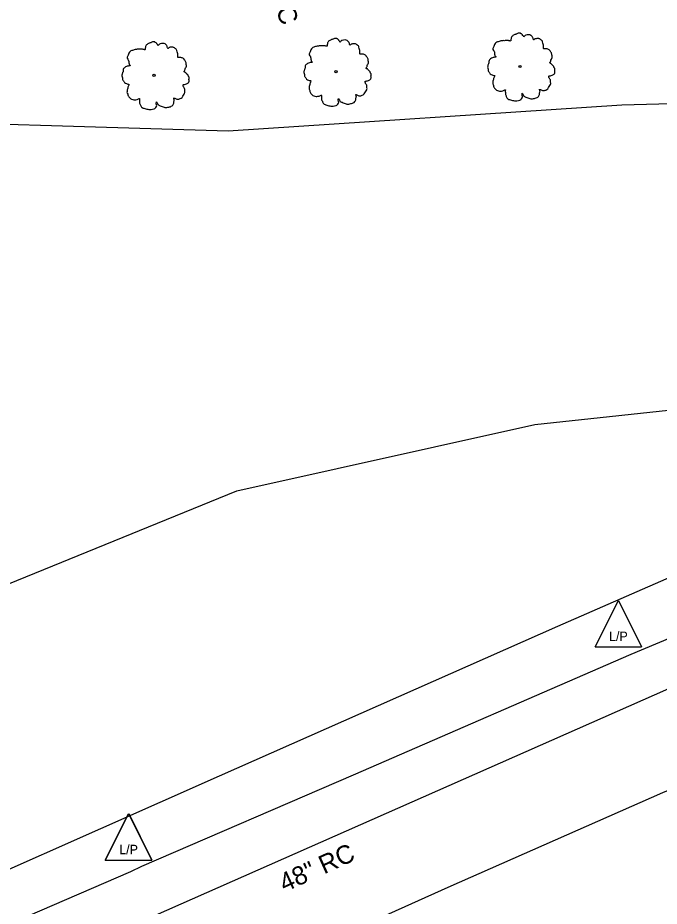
# Model space of a CAD drawing. Extents: x 2004847 to 2009016, y 1134161 to 1140101.
# Drawn here: x 2006951.1 to 2007089.2, y 1137199.9 to 1137391.2 of the extents above; entities that cross this region are included whole.
import ezdxf

# ---------------------------------------------------------------- set-up
doc = ezdxf.new("R2010")
doc.units = 0
for name, color, linetype in [('RD_EX_DR_Pipe', 7, 'Continuous'), ('RD_EX_DR_Pipe_txCode', 7, 'Continuous'), ('RD_EX_Fence_ChLk', 7, 'Continuous'), ('RD_EX_Road', 7, 'Continuous'), ('RD_EX_UT', 7, 'Continuous'), ('RD_EX_VEG', 7, 'Continuous'), ('RD_Sketch3', 7, 'Continuous')]:
    doc.layers.add(name, color=color, linetype=linetype)

msp = doc.modelspace()

# ---------------------------------------------------------------- linework, layer by layer
at = {"layer": 'RD_EX_DR_Pipe'}
msp.add_line((2007177.46, 1137284.68), (2006880.54, 1137153.79), dxfattribs=at)
at = {"layer": 'RD_EX_Fence_ChLk'}
msp.add_lwpolyline([(2006679.24, 1137088.33), (2006760.68, 1137124.45), (2006840.06, 1137159.61), (2006918.41, 1137194.25), (2006994.49, 1137227.96), (2007067.38, 1137260.2), (2007099.31, 1137274.1), (2007109.34, 1137278.47), (2007154.43, 1137298.36), (2007228.48, 1137300.45), (2007306.83, 1137302.12), (2007383.88, 1137303.46)], dxfattribs=at)
at = {"layer": 'RD_EX_Road'}
for points in [[(2006977.78, 1137208.53), (2007023.41, 1137228.21), (2007083.18, 1137254.16), (2007127.4, 1137272.66), (2007144.23, 1137278.54), (2007157.04, 1137281.53), (2007170.48, 1137283.07), (2007177.18, 1137282.69), (2007180.46, 1137282.8), (2007189.97, 1137283.94), (2007250.02, 1137285.07), (2007315.48, 1137286.29), (2007381.64, 1137287.47)], [(2007347.33, 1137031.69), (2007356.56, 1137042.98), (2007358.71, 1137060.56), (2007338.63, 1137108.3), (2007311.34, 1137170.6), (2007285.8, 1137228.92), (2007261.01, 1137249.76), (2007245.66, 1137254.82), (2007196.64, 1137254.34), (2007160.77, 1137251.15), (2007126.25, 1137239.56), (2007089.93, 1137224.32), (2007043.69, 1137203.9), (2006991.12, 1137180.28), (2006988, 1137178.88)], [(2006775.35, 1136676.67), (2006777.94, 1136681.79), (2006766.22, 1136711.06), (2006750.72, 1136746.34), (2006732.8, 1136787.49), (2006716.56, 1136823.39), (2006692.62, 1136878.29), (2006667.71, 1136935.76), (2006658.83, 1136989.32), (2006664.28, 1137021.7), (2006686.47, 1137064.98), (2006711.13, 1137087.73), (2006777.9, 1137121.36), (2006828.33, 1137143.11), (2006876.2, 1137164.06), (2006930.82, 1137188.1), (2006975.41, 1137207.33), (2006977.78, 1137208.53)]]:
    msp.add_lwpolyline(points, dxfattribs=at)
at = {"layer": 'RD_EX_UT'}
for p, q in [((2007075.45, 1137255.72), (2007080.45, 1137265.72)), ((2007080.45, 1137265.72), (2007085.45, 1137255.72)), ((2007075.45, 1137255.72), (2007085.45, 1137255.72)), ((2006969.93, 1137209.81), (2006974.93, 1137219.81)), ((2006969.96, 1137209.83), (2006974.96, 1137219.83)), ((2006974.93, 1137219.81), (2006979.93, 1137209.81)), ((2006974.96, 1137219.83), (2006979.96, 1137209.83)), ((2006969.93, 1137209.81), (2006979.93, 1137209.81)), ((2006969.96, 1137209.83), (2006979.96, 1137209.83))]:
    msp.add_line(p, q, dxfattribs=at)
at = {"layer": 'RD_EX_VEG'}
for points in [[(2007286.19, 1137375.92), (2007274.32, 1137376.1), (2007246.66, 1137372.59), (2007163.36, 1137374.54), (2007081.16, 1137372.35), (2006996.36, 1137366.78), (2006910.64, 1137369.33), (2006829.66, 1137367.22), (2006737.12, 1137362.87)], [(2006471.18, 1137129.79), (2006480.26, 1137120.14), (2006535.33, 1137102.81), (2006642, 1137137.54), (2006697.24, 1137155.67), (2006783.81, 1137195.08), (2006842.32, 1137220.43), (2006911.16, 1137253.85), (2006998.26, 1137289.33), (2007062.47, 1137303.6), (2007136.1, 1137311.49), (2007186.51, 1137309.69), (2007295.5, 1137306.98), (2007351.72, 1137306.99), (2007387.72, 1137305.5)]]:
    msp.add_lwpolyline(points, dxfattribs=at)
for centre, radius in [((2007059.22, 1137380.67), 0.25), ((2007059.2, 1137380.65), 0.0001), ((2006980.44, 1137378.8), 0.25), ((2006980.43, 1137378.78), 0.0001), ((2007019.65, 1137379.54), 0.25), ((2007019.64, 1137379.52), 0.0001)]:
    msp.add_circle(centre, radius, dxfattribs=at)
for points in [[(2007059.35, 1137387.83), (2007059.05, 1137387.86), (2007058.72, 1137387.76), (2007058.47, 1137387.66), (2007058.25, 1137387.58), (2007058.02, 1137387.48), (2007057.72, 1137387.31), (2007057.5, 1137387.11), (2007057.37, 1137386.86), (2007057.32, 1137386.63), (2007057.27, 1137386.36), (2007057.27, 1137386.18), (2007057.15, 1137386.16), (2007057, 1137386.18), (2007056.75, 1137386.26), (2007056.5, 1137386.26), (2007056.25, 1137386.26), (2007055.9, 1137386.23), (2007055.55, 1137386.23), (2007055.27, 1137386.18), (2007054.95, 1137386.14), (2007054.58, 1137386.01), (2007054.23, 1137385.89), (2007053.93, 1137385.64), (2007053.68, 1137385.16), (2007053.55, 1137384.81), (2007053.4, 1137384.56), (2007053.55, 1137384.11), (2007053.73, 1137383.76), (2007053.75, 1137383.56), (2007053.83, 1137383.14), (2007053.93, 1137382.91), (2007054.05, 1137382.71), (2007053.98, 1137382.69), (2007053.6, 1137382.64), (2007053.3, 1137382.54), (2007052.88, 1137382.31), (2007052.65, 1137382.09), (2007052.55, 1137381.76), (2007052.53, 1137381.41), (2007052.43, 1137381.21), (2007052.35, 1137380.94), (2007052.33, 1137380.86), (2007052.28, 1137380.54), (2007052.38, 1137380.09), (2007052.4, 1137379.74), (2007052.53, 1137379.51), (2007052.68, 1137379.34), (2007052.85, 1137379.09), (2007053.25, 1137378.86), (2007053.58, 1137378.76), (2007053.78, 1137378.74), (2007053.6, 1137378.24), (2007053.55, 1137377.89), (2007053.43, 1137377.49), (2007053.43, 1137377.41), (2007053.38, 1137376.94), (2007053.53, 1137376.61), (2007053.6, 1137376.24), (2007053.78, 1137376.01), (2007054.05, 1137375.71), (2007054.38, 1137375.49), (2007054.87, 1137375.36), (2007055.27, 1137375.39), (2007055.85, 1137375.56), (2007056.1, 1137375.64), (2007056.07, 1137375.46), (2007056.1, 1137375.09), (2007056.1, 1137374.67), (2007056.25, 1137374.34), (2007056.35, 1137374.07), (2007056.5, 1137373.82), (2007056.82, 1137373.59), (2007057.22, 1137373.52), (2007057.65, 1137373.37), (2007058.1, 1137373.29), (2007058.6, 1137373.27), (2007059.2, 1137373.42), (2007059.47, 1137373.54), (2007059.57, 1137373.72), (2007059.77, 1137374.09), (2007059.72, 1137374.32), (2007059.75, 1137374.91), (2007059.85, 1137374.74), (2007060.02, 1137374.39), (2007060.52, 1137374.09), (2007060.92, 1137373.92), (2007061.4, 1137373.77), (2007061.7, 1137373.69), (2007062.17, 1137373.77), (2007062.55, 1137373.84), (2007062.92, 1137373.97), (2007063.22, 1137374.24), (2007063.4, 1137374.52), (2007063.45, 1137374.79), (2007063.52, 1137375.16), (2007063.57, 1137375.34)], [(2007063.57, 1137375.34), (2007063.5, 1137375.51), (2007063.45, 1137375.76), (2007063.52, 1137375.74), (2007063.7, 1137375.69), (2007063.97, 1137375.56), (2007064.2, 1137375.49), (2007064.52, 1137375.51), (2007064.8, 1137375.61), (2007065.25, 1137375.89), (2007065.52, 1137376.36), (2007065.8, 1137376.76), (2007065.87, 1137377.09), (2007065.82, 1137377.31), (2007065.8, 1137377.81), (2007065.6, 1137378.06), (2007065.55, 1137378.19), (2007065.45, 1137378.59), (2007065.52, 1137378.64), (2007065.8, 1137378.69), (2007066.17, 1137378.81), (2007066.44, 1137378.94), (2007066.67, 1137379.11), (2007066.74, 1137379.34), (2007066.72, 1137379.74), (2007066.77, 1137380.14), (2007066.69, 1137380.29), (2007066.59, 1137380.44), (2007066.52, 1137380.64), (2007066.37, 1137380.79), (2007066.27, 1137380.94), (2007066.17, 1137381.04), (2007066.05, 1137381.19), (2007065.87, 1137381.31), (2007065.72, 1137381.36), (2007065.67, 1137381.51), (2007065.82, 1137381.71), (2007065.87, 1137381.81), (2007065.9, 1137382.04), (2007066.12, 1137382.39), (2007066.17, 1137382.79), (2007066.12, 1137383.21), (2007066.07, 1137383.49), (2007065.92, 1137383.76), (2007065.72, 1137384.01), (2007065.6, 1137384.19), (2007065.42, 1137384.31), (2007065.1, 1137384.44), (2007064.85, 1137384.49), (2007064.5, 1137384.49), (2007064.3, 1137384.54), (2007064.32, 1137384.59), (2007064.32, 1137384.74), (2007064.32, 1137385.01), (2007064.25, 1137385.46), (2007064.1, 1137385.96), (2007064.1, 1137385.99), (2007064, 1137386.23), (2007063.77, 1137386.43), (2007063.6, 1137386.53), (2007063.4, 1137386.66), (2007063.15, 1137386.68), (2007062.85, 1137386.68), (2007062.57, 1137386.63), (2007062.37, 1137386.53), (2007062.2, 1137386.41), (2007062.12, 1137386.56), (2007062.02, 1137386.86), (2007061.97, 1137387.01), (2007061.82, 1137387.18), (2007061.6, 1137387.38), (2007061.15, 1137387.51), (2007060.52, 1137387.43), (2007060.22, 1137387.23), (2007060.07, 1137387.06), (2007060.02, 1137387.18), (2007059.82, 1137387.38), (2007059.72, 1137387.56), (2007059.55, 1137387.68), (2007059.4, 1137387.78), (2007059.3, 1137387.83)], [(2006980.57, 1137385.97), (2006980.27, 1137385.99), (2006979.95, 1137385.89), (2006979.7, 1137385.79), (2006979.47, 1137385.72), (2006979.25, 1137385.62), (2006978.95, 1137385.44), (2006978.72, 1137385.24), (2006978.6, 1137384.99), (2006978.55, 1137384.77), (2006978.5, 1137384.49), (2006978.5, 1137384.32), (2006978.37, 1137384.29), (2006978.22, 1137384.32), (2006977.97, 1137384.39), (2006977.72, 1137384.39), (2006977.47, 1137384.39), (2006977.12, 1137384.37), (2006976.77, 1137384.37), (2006976.5, 1137384.32), (2006976.17, 1137384.27), (2006975.8, 1137384.14), (2006975.45, 1137384.02), (2006975.15, 1137383.77), (2006974.9, 1137383.29), (2006974.77, 1137382.94), (2006974.62, 1137382.69), (2006974.77, 1137382.24), (2006974.95, 1137381.9), (2006974.97, 1137381.7), (2006975.05, 1137381.27), (2006975.15, 1137381.05), (2006975.27, 1137380.85), (2006975.2, 1137380.82), (2006974.82, 1137380.77), (2006974.52, 1137380.67), (2006974.1, 1137380.45), (2006973.87, 1137380.22), (2006973.77, 1137379.9), (2006973.75, 1137379.55), (2006973.65, 1137379.35), (2006973.57, 1137379.07), (2006973.55, 1137379), (2006973.5, 1137378.67), (2006973.6, 1137378.22), (2006973.62, 1137377.87), (2006973.75, 1137377.65), (2006973.9, 1137377.47), (2006974.07, 1137377.22), (2006974.47, 1137377), (2006974.8, 1137376.9), (2006975, 1137376.87), (2006974.82, 1137376.37), (2006974.77, 1137376.02), (2006974.65, 1137375.62), (2006974.65, 1137375.55), (2006974.6, 1137375.07), (2006974.75, 1137374.75), (2006974.82, 1137374.37), (2006975, 1137374.15), (2006975.27, 1137373.85), (2006975.6, 1137373.62), (2006976.1, 1137373.5), (2006976.5, 1137373.52), (2006977.07, 1137373.7), (2006977.32, 1137373.77), (2006977.3, 1137373.6), (2006977.32, 1137373.22), (2006977.32, 1137372.8), (2006977.47, 1137372.47), (2006977.57, 1137372.2), (2006977.72, 1137371.95), (2006978.05, 1137371.72), (2006978.45, 1137371.65), (2006978.87, 1137371.5), (2006979.32, 1137371.42), (2006979.82, 1137371.4), (2006980.42, 1137371.55), (2006980.7, 1137371.67), (2006980.8, 1137371.85), (2006981, 1137372.22), (2006980.95, 1137372.45), (2006980.97, 1137373.05), (2006981.07, 1137372.87), (2006981.25, 1137372.52), (2006981.75, 1137372.22), (2006982.15, 1137372.05), (2006982.62, 1137371.9), (2006982.92, 1137371.82), (2006983.39, 1137371.9), (2006983.77, 1137371.97), (2006984.14, 1137372.1), (2006984.44, 1137372.37), (2006984.62, 1137372.65), (2006984.67, 1137372.92), (2006984.74, 1137373.3), (2006984.79, 1137373.47)], [(2006984.79, 1137373.47), (2006984.72, 1137373.65), (2006984.67, 1137373.9), (2006984.74, 1137373.87), (2006984.92, 1137373.82), (2006985.19, 1137373.7), (2006985.42, 1137373.62), (2006985.74, 1137373.65), (2006986.02, 1137373.75), (2006986.47, 1137374.02), (2006986.74, 1137374.5), (2006987.02, 1137374.9), (2006987.09, 1137375.22), (2006987.04, 1137375.45), (2006987.02, 1137375.95), (2006986.82, 1137376.2), (2006986.77, 1137376.32), (2006986.67, 1137376.72), (2006986.74, 1137376.77), (2006987.02, 1137376.82), (2006987.39, 1137376.95), (2006987.67, 1137377.07), (2006987.89, 1137377.25), (2006987.97, 1137377.47), (2006987.94, 1137377.87), (2006987.99, 1137378.27), (2006987.92, 1137378.42), (2006987.82, 1137378.57), (2006987.74, 1137378.77), (2006987.59, 1137378.92), (2006987.49, 1137379.07), (2006987.39, 1137379.17), (2006987.27, 1137379.32), (2006987.09, 1137379.45), (2006986.94, 1137379.5), (2006986.89, 1137379.65), (2006987.04, 1137379.85), (2006987.09, 1137379.95), (2006987.12, 1137380.17), (2006987.34, 1137380.52), (2006987.39, 1137380.92), (2006987.34, 1137381.35), (2006987.29, 1137381.62), (2006987.14, 1137381.9), (2006986.94, 1137382.14), (2006986.82, 1137382.32), (2006986.64, 1137382.44), (2006986.32, 1137382.57), (2006986.07, 1137382.62), (2006985.72, 1137382.62), (2006985.52, 1137382.67), (2006985.54, 1137382.72), (2006985.54, 1137382.87), (2006985.54, 1137383.14), (2006985.47, 1137383.59), (2006985.32, 1137384.09), (2006985.32, 1137384.12), (2006985.22, 1137384.37), (2006984.99, 1137384.57), (2006984.82, 1137384.67), (2006984.62, 1137384.79), (2006984.37, 1137384.82), (2006984.07, 1137384.82), (2006983.79, 1137384.77), (2006983.59, 1137384.67), (2006983.42, 1137384.54), (2006983.34, 1137384.69), (2006983.24, 1137384.99), (2006983.19, 1137385.14), (2006983.04, 1137385.32), (2006982.82, 1137385.52), (2006982.37, 1137385.64), (2006981.75, 1137385.57), (2006981.45, 1137385.37), (2006981.3, 1137385.19), (2006981.25, 1137385.32), (2006981.05, 1137385.52), (2006980.95, 1137385.69), (2006980.77, 1137385.82), (2006980.62, 1137385.92), (2006980.52, 1137385.97)], [(2007019.78, 1137386.7), (2007019.48, 1137386.73), (2007019.16, 1137386.63), (2007018.91, 1137386.53), (2007018.68, 1137386.45), (2007018.46, 1137386.35), (2007018.16, 1137386.18), (2007017.93, 1137385.98), (2007017.81, 1137385.73), (2007017.76, 1137385.5), (2007017.71, 1137385.23), (2007017.71, 1137385.05), (2007017.58, 1137385.03), (2007017.43, 1137385.05), (2007017.18, 1137385.13), (2007016.93, 1137385.13), (2007016.68, 1137385.13), (2007016.33, 1137385.1), (2007015.98, 1137385.1), (2007015.71, 1137385.05), (2007015.38, 1137385), (2007015.01, 1137384.88), (2007014.66, 1137384.75), (2007014.36, 1137384.5), (2007014.11, 1137384.03), (2007013.98, 1137383.68), (2007013.83, 1137383.43), (2007013.98, 1137382.98), (2007014.16, 1137382.63), (2007014.18, 1137382.43), (2007014.26, 1137382.01), (2007014.36, 1137381.78), (2007014.48, 1137381.58), (2007014.41, 1137381.56), (2007014.03, 1137381.51), (2007013.73, 1137381.41), (2007013.31, 1137381.18), (2007013.08, 1137380.96), (2007012.98, 1137380.63), (2007012.96, 1137380.28), (2007012.86, 1137380.08), (2007012.78, 1137379.81), (2007012.76, 1137379.73), (2007012.71, 1137379.41), (2007012.81, 1137378.96), (2007012.83, 1137378.61), (2007012.96, 1137378.38), (2007013.11, 1137378.21), (2007013.28, 1137377.96), (2007013.68, 1137377.73), (2007014.01, 1137377.63), (2007014.21, 1137377.61), (2007014.03, 1137377.11), (2007013.98, 1137376.76), (2007013.86, 1137376.36), (2007013.86, 1137376.28), (2007013.81, 1137375.81), (2007013.96, 1137375.48), (2007014.03, 1137375.11), (2007014.21, 1137374.88), (2007014.48, 1137374.58), (2007014.81, 1137374.36), (2007015.31, 1137374.23), (2007015.71, 1137374.26), (2007016.28, 1137374.43), (2007016.53, 1137374.51), (2007016.51, 1137374.33), (2007016.53, 1137373.96), (2007016.53, 1137373.53), (2007016.68, 1137373.21), (2007016.78, 1137372.93), (2007016.93, 1137372.68), (2007017.26, 1137372.46), (2007017.66, 1137372.38), (2007018.08, 1137372.23), (2007018.53, 1137372.16), (2007019.03, 1137372.13), (2007019.63, 1137372.28), (2007019.9, 1137372.41), (2007020, 1137372.58), (2007020.2, 1137372.96), (2007020.15, 1137373.18), (2007020.18, 1137373.78), (2007020.28, 1137373.61), (2007020.45, 1137373.26), (2007020.95, 1137372.96), (2007021.35, 1137372.78), (2007021.83, 1137372.63), (2007022.13, 1137372.56), (2007022.6, 1137372.63), (2007022.98, 1137372.71), (2007023.35, 1137372.83), (2007023.65, 1137373.11), (2007023.83, 1137373.38), (2007023.88, 1137373.66), (2007023.95, 1137374.03), (2007024, 1137374.21)], [(2007024, 1137374.21), (2007023.93, 1137374.38), (2007023.88, 1137374.63), (2007023.95, 1137374.61), (2007024.13, 1137374.56), (2007024.4, 1137374.43), (2007024.63, 1137374.36), (2007024.95, 1137374.38), (2007025.23, 1137374.48), (2007025.68, 1137374.76), (2007025.95, 1137375.23), (2007026.23, 1137375.63), (2007026.3, 1137375.96), (2007026.25, 1137376.18), (2007026.23, 1137376.68), (2007026.03, 1137376.93), (2007025.98, 1137377.06), (2007025.88, 1137377.46), (2007025.95, 1137377.51), (2007026.23, 1137377.56), (2007026.6, 1137377.68), (2007026.88, 1137377.81), (2007027.1, 1137377.98), (2007027.18, 1137378.21), (2007027.15, 1137378.61), (2007027.2, 1137379.01), (2007027.13, 1137379.16), (2007027.03, 1137379.31), (2007026.95, 1137379.51), (2007026.8, 1137379.66), (2007026.7, 1137379.81), (2007026.6, 1137379.91), (2007026.48, 1137380.06), (2007026.3, 1137380.18), (2007026.15, 1137380.23), (2007026.1, 1137380.38), (2007026.25, 1137380.58), (2007026.3, 1137380.68), (2007026.33, 1137380.91), (2007026.55, 1137381.26), (2007026.6, 1137381.66), (2007026.55, 1137382.08), (2007026.5, 1137382.36), (2007026.35, 1137382.63), (2007026.15, 1137382.88), (2007026.03, 1137383.05), (2007025.85, 1137383.18), (2007025.53, 1137383.3), (2007025.28, 1137383.35), (2007024.93, 1137383.35), (2007024.73, 1137383.4), (2007024.75, 1137383.45), (2007024.75, 1137383.6), (2007024.75, 1137383.88), (2007024.68, 1137384.33), (2007024.53, 1137384.83), (2007024.53, 1137384.85), (2007024.43, 1137385.1), (2007024.2, 1137385.3), (2007024.03, 1137385.4), (2007023.83, 1137385.53), (2007023.58, 1137385.55), (2007023.28, 1137385.55), (2007023, 1137385.5), (2007022.8, 1137385.4), (2007022.63, 1137385.28), (2007022.55, 1137385.43), (2007022.45, 1137385.73), (2007022.4, 1137385.88), (2007022.25, 1137386.05), (2007022.03, 1137386.25), (2007021.58, 1137386.38), (2007020.95, 1137386.3), (2007020.65, 1137386.1), (2007020.5, 1137385.93), (2007020.45, 1137386.05), (2007020.25, 1137386.25), (2007020.15, 1137386.43), (2007019.98, 1137386.55), (2007019.83, 1137386.65), (2007019.73, 1137386.7)]]:
    msp.add_spline(points, degree=3, dxfattribs=at)

# ---------------------------------------------------------------- texts
at = {"layer": 'RD_EX_DR_Pipe_txCode'}
msp.add_text('48" RC', height=4, rotation=24.4972, dxfattribs=at).set_placement((2007008.54, 1137202.85))
at = {"layer": 'RD_EX_UT'}
for p in [(2007078.44, 1137257), (2006972.92, 1137211.09), (2006972.95, 1137211.11)]:
    msp.add_text('L/P', height=2, dxfattribs=at).set_placement(p)
at = {"layer": 'RD_Sketch3'}
msp.add_text('CONC', height=4, rotation=289.4494, dxfattribs=at).set_placement((2007002.67, 1137404.13))

doc.saveas('drawing.dxf')
